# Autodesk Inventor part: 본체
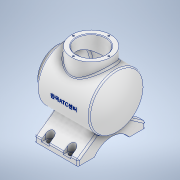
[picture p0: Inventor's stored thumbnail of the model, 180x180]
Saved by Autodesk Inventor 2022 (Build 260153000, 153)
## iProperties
Created: 2023-04
Part Number: 본체
Material: 알루미늄 6061
Document SubType Name: Modeling
Designer: Admin
Mass: 1295.51 g
Surface Area: 1065.12 cm^2
Volume: 479.817 cm^3
Density: 2.7 g/cm^3
Appearance: 알루미늄 - 평지
Author: Admin
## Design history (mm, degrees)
sketch "스케치1"
  geometry: L1 (-84.575, 0)-(87.453, 0) reference; L2 (0, -10.134)-(0, 60.805) reference; L3 (-60, 0)-(-48, 0); L4 (-48, 0)-(-48, 36); L5 (-48, 36)-(-60, 36); L6 (-60, 36)-(-60, 0); L7 (-48, 0)-(-31.477, 0); L8 (-31.477, 0)-(10.095, 0); L9 (10.095, 0)-(13.571, 0); L10 (-48, 0)-(48.336, 0); L11 (48.336, 0)-(48.336, 50); L12 (48.336, 50)-(-48, 50); L13 (-48, 50)-(-48, 0); L14 (48.336, 0)-(60, 0); A1 r 113 centre (-53, 0) between (60, 0) and (48.336, 50); 3 further points
  constraints: 24 end point, 5 horizontal, 4 parallel, 3 point on line, 2 perpendicular, 2 point on circle, 1 centre point, 1 symmetric about line
  dimensions: "d0" = 72 diameter of L5 L1; "d6" = 50 distance of L10.end L11.end; "d8" = 108 distance edge to line of A1 L13; "d9" = 120 dimension on A1 L6; "d10" = 226 diameter of A1
revolve "회전1" sketch "스케치1" stored, may be unused: angle "d11" = 90 deg
sketch "스케치3"
  geometry: L1 (-93.622, 0)-(90.395, 0); L2 (-60, -36)-(-60, 36) reference; L3 (-60, 0)-(-41, 0); L4 (-41, 0)-(-41, 27); L5 (-41, 27)-(-60, 27); L6 (-60, 27)-(-60, 0); L7 (-41, 0)-(43.887, 0); L8 (43.887, 0)-(43.887, 43); L9 (43.887, 43)-(-41, 43); L10 (-41, 43)-(-41, 0); L11 (43.887, 0)-(53, 0); L12 (53, 0)-(60, 0); A1 r 106 centre (-53, 0) between (53, 0) and (43.887, 43); A2 r 113 centre (-53, 0) between (48.336, -50) and (48.336, 50) reference; 3 further points
  constraints: 22 end point, 4 parallel, 3 horizontal, 3 point on circle, 3 point on line, 2 perpendicular, 1 centre point, 1 midpoint
  dimensions: "d12" = 212 diameter of A1; "d13" = 54 diameter of L5 L1; "d14" = 86 diameter of L9 L1; "d15" = 19 distance of L4.end L5.end; "d17" = 7 distance of L11.end L12.end
revolve "회전2" sketch "스케치3" stored, may be unused: angle "d18" = 90 deg
node "작업 평면1"
sketch "스케치4"
  geometry: L1 (60, 36)-(60, -36) reference; L2 (79.6, 0)-(-57.6, 0) reference; C1 r 36 at (-2, 0); 1 further point
  constraints: 1 centre point, 1 point on line
  dimensions: "d20" = 62 distance from line of C1.centre L1; "d21" = 72 diameter of C1
extrude "돌출1" join sketch "스케치4" stored distance "d22" = 10; taper "d23" = 0 deg
sketch "스케치5"
  geometry: C1 r 36 at (0, 0) reference; C2 r 27 at (0, 0); 1 further point
  constraints: 1 centre point, 1 coincident
  dimensions: "d24" = 54 diameter of C2
extrude "돌출2" cut sketch "스케치5" stored distance "d25" = 10; taper "d26" = 0 deg
sketch "스케치7" dims "d63" = 65
  geometry: 3 further points
  constraints: 2 vertical alignment, 1 coincident, 2 other
hole "구멍1" sketch "스케치7" at (0, 32.5) diameter "d64" = 3.242; stored, may be unused: countersink angle "d68" = 90 deg, drill point angle "d70" = 118 deg; dims "d65" = 8, "d66" = 4, "d67" = 2, "d69" = 10
sketch "스케치8" dims "d74" = 65
  geometry: C1 r 27 at (0, 0) reference; 3 further points
  constraints: 2 horizontal alignment, 1 coincident, 2 other
hole "구멍2" sketch "스케치8" at (32.5, 0) diameter "d75" = 3.242; stored, may be unused: countersink angle "d79" = 90 deg, drill point angle "d81" = 118 deg; dims "d76" = 8, "d77" = 4, "d78" = 2, "d80" = 10
node "작업 평면2"
sketch "스케치12"
  geometry: L1 (27, 51.324)-(27, 80.958); L2 (13, 52.982)-(13, 80.958); L3 (27, 80.958)-(13, 80.958); C1 r 4.5 at (20, 53) reference; C2 r 7 at (20, 53); 3 further points
  constraints: 6 end point, 2 tangent, 2 vertical, 1 centre point, 1 coincident, 1 perpendicular
  dimensions: "d93" = 14 diameter of C2
extrude "돌출5" cut sketch "스케치12" distance "d94" = 19.5; taper "d95" = 0 deg
chamfer "모따기1" distance "d96" = 1; stored, may be unused: second distance "d97" = 2, angle "d98" = 45 deg
node "작업 평면6"
fillet "모깎기2" dims "d134" = 3
fillet "모깎기3" dims "d135" = 3
fillet "모깎기4" dims "d136" = 3
sketch "스케치21"
  geometry: 1 further point
node "작업 평면7"
sketch "스케치22"
  geometry: L1 (-60, -36)-(-60, 36) reference; L2 (-72.4, 0)-(14.4, 0) reference; 2 further points
  constraints: 1 point on line, 1 other
  dimensions: "d138" = 62 distance from line of L1 point (2, 0)
feature "엠보싱1" sketch "스케치22" dims "d12" = 212, "d13" = 54, "d14" = 86, "d15" = 19, "d17" = 7, "d139" = 0.5, "d140" = 0
node "작업 평면8"
sketch "스케치23"
  geometry: L1 (-102.4, 0)-(75.4, 0) reference; L2 (0, -72.4)-(0, 84.4) reference; L3 (-77, 0)-(-77, 62); L4 (-77, 62)-(-67, 62); L5 (-67, 62)-(-42.278, 26.694); L6 (-77, 0)-(-50, 0); A1 r 50 centre (0, 0) between (-42.278, 26.694) and (-50, 0); 2 further points
  constraints: 8 end point, 2 point on circle, 2 point on line, 1 centre point, 1 coincident, 1 perpendicular, 1 vertical, 2 other
  dimensions: "d142" = 77 distance between parallel lines of L3 L2; "d143" = 10 distance of L3.end L4.end; "d144" = 55 deg angle of L5 L4; "d145" = 62 distance between parallel lines of L1 L4
extrude "돌출11" join sketch "스케치23" distance "d146" = 80; taper "d147" = 0 deg
sketch "스케치24"
  geometry: L1 (62, -77)-(0, -77) reference; L2 (38.5, -77)-(38.5, -72.118); L3 (0, -177.4)-(0, 105.4) reference; C1 r 38.5 at (0, -98.5); 1 further point
  constraints: 2 end point, 2 point on line, 1 centre point, 1 perpendicular, 1 tangent
  dimensions: "d150" = 38.5 distance from line of L2 C1.centre; "d151" = 17 distance edge to line of C1 L1
extrude "돌출12" cut sketch "스케치24" extent not by distance; stored distance "d152" = 0; taper "d153" = 0 deg
sketch "스케치25"
  geometry: L1 (80, 0)-(80, -30.063) reference; L2 (0, 0)-(80, 0) reference; L3 (0, 0)-(0, -30.063) reference; C1 r 4.5 at (20, -8); C2 r 4.5 at (60, -8); 1 further point
  constraints: 2 centre point
  dimensions: "d154" = 20 distance from line of L1 C2.centre; "d155" = 8 distance from line of L2 C2.centre; "d156" = 8 distance from line of L2 C1.centre; "d157" = 20 distance from line of C1.centre L3; "d158" = 9 diameter of C1; "d159" = 9 diameter of C2
extrude "돌출13" cut sketch "스케치25" distance "d160" = 6; taper "d161" = 0 deg
sketch "스케치26"
  geometry: C1 r 4.5 at (0, 0) reference; C2 r 4.5 at (40, 0) reference; C3 r 7 at (0, 0); C4 r 7 at (40, 0); 1 further point
  constraints: 2 centre point, 2 coincident
  dimensions: "d162" = 14 diameter of C4; "d163" = 14 diameter of C3
extrude "돌출14" cut sketch "스케치26" distance "d164" = 15; taper "d165" = 0 deg
sketch "스케치27" dims "d166" = 14
  geometry: L1 (-7, 0.601)-(-7, -16.919); L2 (-7, -16.919)-(7, -16.919); L3 (7, -16.919)-(7, 0); C1 r 4.5 at (0, 0) reference; 3 further points
  constraints: 6 end point, 4 vertical, 1 coincident, 1 perpendicular, 3 other
extrude "돌출15" cut sketch "스케치27" distance "d167" = 15; taper "d168" = 0 deg
fillet "모깎기5" dims "d169" = 3
node "솔리드1"
pattern_circular "원형 패턴1" dims angle "d72" = 360 deg
pattern_circular "원형 패턴2" dims angle "d83" = 360 deg
mirror "미러2"
mirror "미러3"
mirror "미러7"
mirror "미러8"
mirror "미러9"
node "투영된 루프4"
node "투영된 루프5"
feature "A9D066F2-1C7D-4E18-AEED-F7BC21143FA4" dims "d64" = 3.242, "d65" = 8, "d66" = 4, "d67" = 2, "d68" = 90 deg, "d69" = 10, "d70" = 118 deg
other parameters: "d19" = 65, "d39" = 77, "d43" = 17, "d49" = 17, "d92" = -51.75, "d137" = 121.75
